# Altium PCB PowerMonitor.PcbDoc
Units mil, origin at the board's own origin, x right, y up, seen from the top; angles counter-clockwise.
Board outline 3500 x 2200 mil, 2 copper layers (Top Layer, Bottom Layer); 24 components, 15 nets, 81 pads, 2 vias.
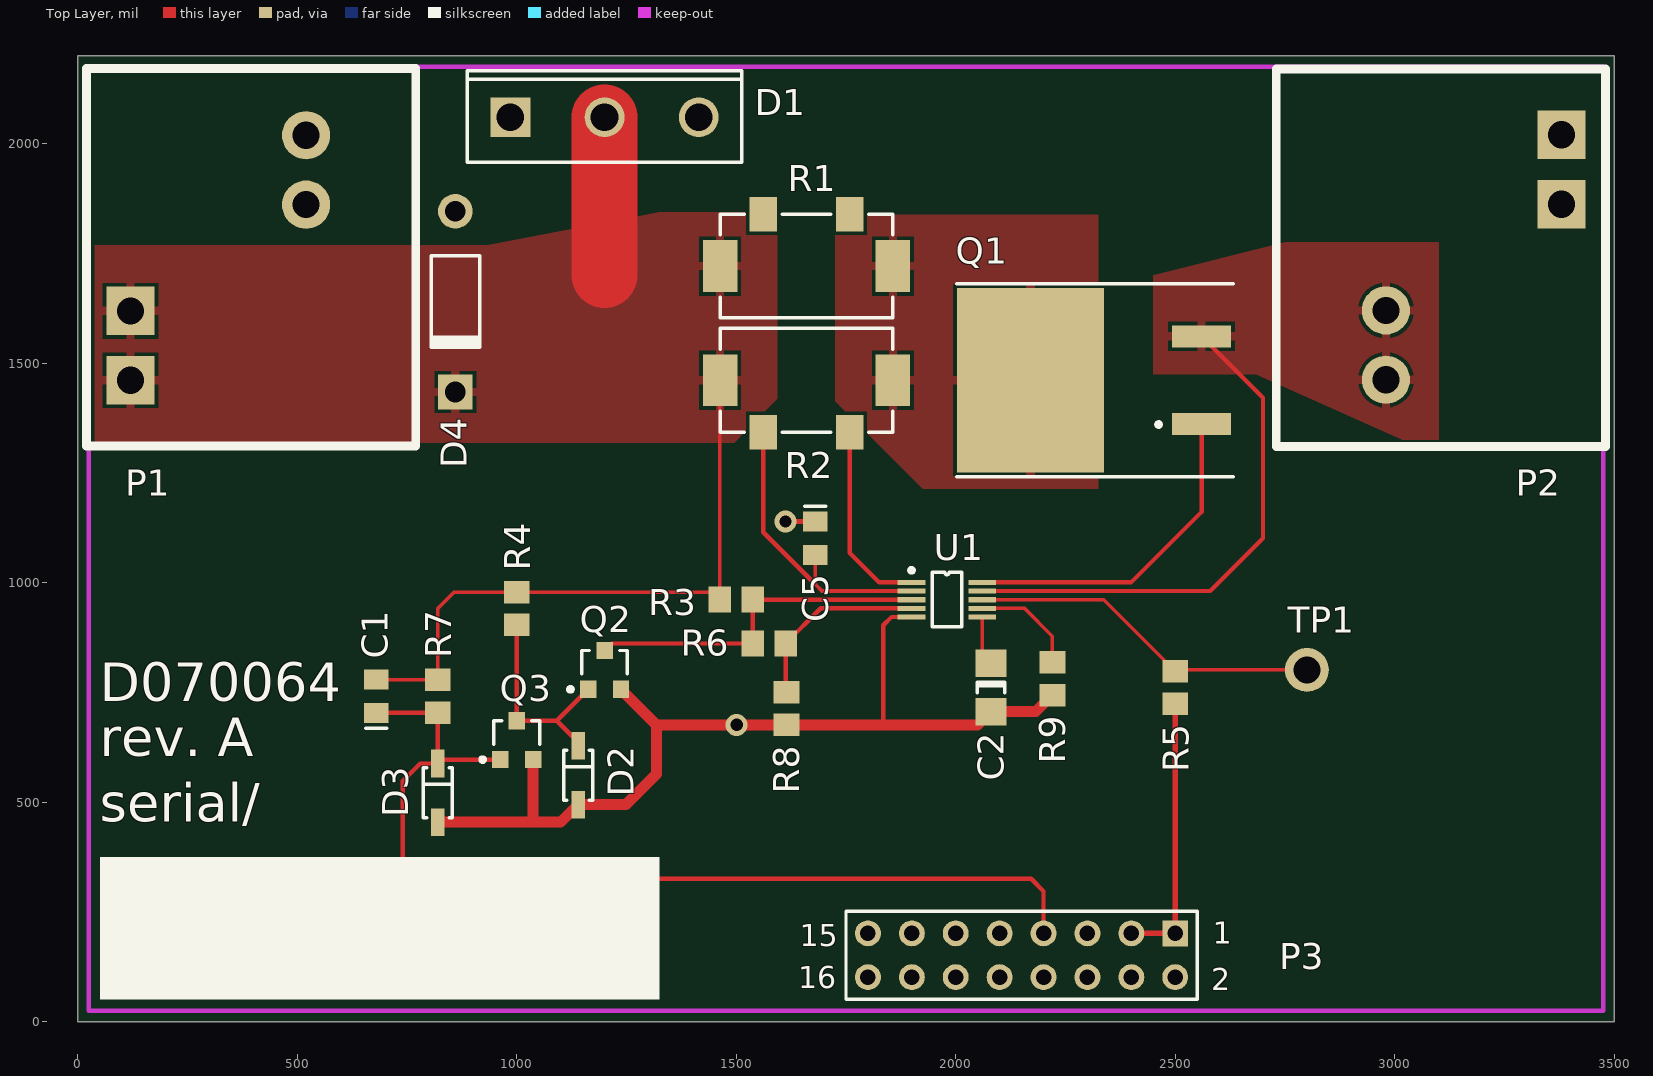
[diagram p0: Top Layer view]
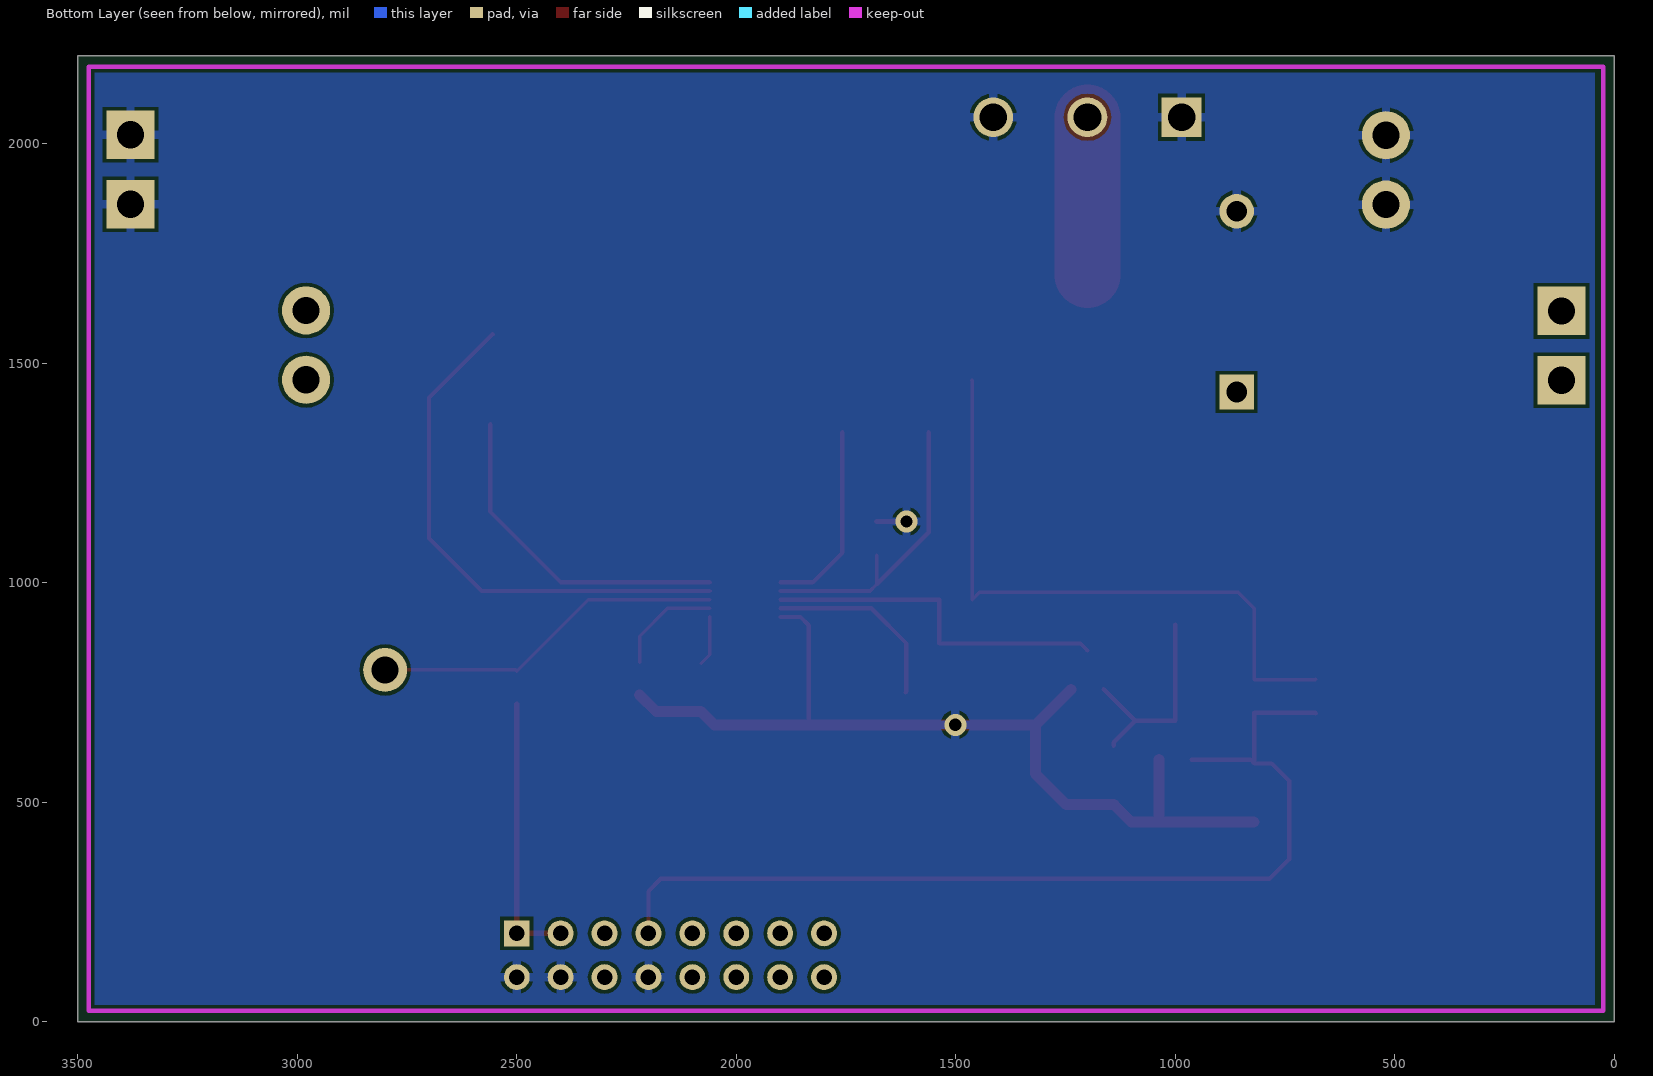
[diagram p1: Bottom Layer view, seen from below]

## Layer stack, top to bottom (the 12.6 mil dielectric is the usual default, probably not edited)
Top Layer: signal copper 1.4
Dielectric: dielectric 12.6, FR-4, Dk 4.8
Bottom Layer: signal copper 1.4

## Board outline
0,0 0,2200 3500,2200 3500,0

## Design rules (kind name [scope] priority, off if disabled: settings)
Clearance [All] p1: gap=8
ComponentClearance [All] p1: gap=10 collisioncheckmode=3 verticalgap=10
Height [All] p1: minheight=0 maxheight=2000 prefheight=500
HoleSize [All] p1: absolutevalues=TRUE maxlimit=125 minlimit=1 maxpercent=80.000 minpercent=20.000
PolygonConnect [All] p1: connectstyle=Relief reliefconductorwidth=20 reliefentries=4 polygonreliefangle="90 Angle"
RoutingVias [All] p1: holewidth=25 width=40 viastyle="Through Hole" minholewidth=28 minwidth=50 maxholewidth=28 maxwidth=50
SolderMaskExpansion [All] p1: expansion=4
TestPointUsage [All] p1: valid=0 allowmultiple=FALSE
Testpoint [All] p1: side=15 testpointundercomponent=TRUE minsize=40 maxsize=100 preferedsize=60 minholesize=0 maxholesize=40 preferedholesize=32 testpointgrid=1 style=1023 order=0123456789
Width [All] p1: maxlimit=400 minlimit=8 preferedwidth=8
16 further rules are at their usual default settings.

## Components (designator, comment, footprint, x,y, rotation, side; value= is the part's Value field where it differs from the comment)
C1 "10p" CC2013-0805 680,741 r90 top
C2 "6.8u" CC3216-1206 2080,761 r270 top
C5 "1n" CC2013-0805 1680,1101 r270 top
D1 "63CPQ100" TO-247AC 1200,2060 r0 top
D2 "zener diode" DO-SOD123 1140,561 r90 top
D3 "zener diode" DO-SOD123 820,521 r90 top
D4 "zener diode" DO-41 860,1640 r270 top
P1 "TBlock_10.16_2" TBLOCK-10.16-2 120,1461 r90 top
P2 "TBlock_10.16_2" TBLOCK-10.16-2 3380,2020 r270 top
P3 "Header 8X2" HDR2X8 2500,201 r180 top
Q1 "FDB3632" D2PAK 2380,1461 r90 top
Q2 "BSS123" SO-G3/C2.25 1200,801 r0 top
Q3 "BSS123" SO-G3/C2.25 1000,641 r0 top
R1 "0.01" RW10862-4325 1660,1721 r180 top
R2 "0.005" RW10862-4325 1660,1461 r0 top
R3 "100K" CR2012-0805 1500,961 r180 top
R4 "100K" CR2012-0805 1000,941 r90 top
R5 "20K" CR2012-0805 2500,761 r270 top
R6 "6.04K" CR2012-0805 1575,861 r180 top
R7 "100K" CR2012-0805 820,741 r90 top
R8 "3.9K" CR2012-0805 1614,713 r90 top
R9 "20K" CR2012-0805 2220,781 r90 top
TP1 "Testpoint" TP1 2800,801 r0 top
U1 "LM5069" TSSO3x5-G10 1980,961 r270 top

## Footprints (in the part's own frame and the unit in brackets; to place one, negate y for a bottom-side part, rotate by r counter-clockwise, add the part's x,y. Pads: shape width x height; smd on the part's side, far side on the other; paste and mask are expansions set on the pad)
CC2013-0805 [mm] "Chip Capacitor; Body 2.0 x 1.3 mm (LxW typ)"
  rect 1.15x1.4 smd: 1(-0.975,0) 2(0.975,0)
  silkscreen extent -1.85,-0.6 -1.85,0.6
CC3216-1206 [mm] "Chip Capacitor; Body 3.2 x 1.6 mm (LxW typ)"
  rect 1.6x1.8 smd: 1(-1.4,0) 2(1.4,0)
  silkscreen extent -0.3,-0.8 0.3,0.8
CR2012-0805 [mm] "Chip Resistor; Body 2.0 x 1.3 mm (LxW typ)"
  rect 1.3x1.5 smd: 1(-0.95,0) 2(0.95,0)
D2PAK [mil] "D2-PAK/TO-263-AB; 3 Leads (1 Cropped); Body 15.5 (inc. leads) x 10.5 mm (LxW max)"
  rect 50x135 smd: 1(-100,-180) 3(100,-180)
  rect 420x335 smd: 2(0,210)
  silkscreen extent -219,-252 219,378
DO-41 [mm] "Diode, Axial; Body 5.2 x 2.7 mm (LxDia. max), Lead Dia. 0.86 mm (max)"
  round 2 hole 1.2: 1(-5.23,0)
  rect 2x2 hole 1.2: 2(5.23,0)
  silkscreen extent -2.65,-1.4 2.75,1.4
DO-SOD123 [mm] "SOD-123; 2 Leads; Body 2.7 x 1.6 mm, (LxW)"
  rect 1.6x0.8 smd: 1(-1.7,0) 2(1.7,0)
  silkscreen extent -1.45,-0.85 1.45,0.85
HDR2X8 [mm] "Connector; Header; 8x2 Position"
  rect 1.5x1.5 hole 0.9: 1(0,0)
  round 1.5 hole 0.9: 2(0,2.54) 3(2.54,0) 4(2.54,2.54) 5(5.08,0) 6(5.08,2.54) 7(7.62,0) 8(7.62,2.54) 9(10.16,0) 10(10.16,2.54) 11(12.7,0) 12(12.7,2.54) 13(15.24,0) 14(15.24,2.54) 15(17.78,0) 16(17.78,2.54)
  silkscreen extent -1.27,-1.27 19.05,3.81
RW10862-4325 [mm] "Current Sense Resistor; Body 10.8 x 6.2 mm (LxW typ)"
  rect 2x3 smd: 1(-5,0) 4(5,0)
  rect 1.6x2 smd: 2(-2.5,-3) 3(2.5,-3)
  silkscreen extent -5,-3 5,3
SO-G3/C2.25 [mm] "SOT-23; 3 Leads; Body 3.0 x 2.5 mm, inc. leads (LxW max)"
  rect 0.95x1 smd: 1(-0.95,-1.125) 2(0.95,-1.125) 3(0,1.125)
  silkscreen extent -2.1,-1.25 1.32,1.13
TBLOCK-10.16-2 [mil] "Terminal Block, 10.16mm, 2pin"
  rect 110x110 hole 62: 1(0,0) 1(158,0)
  round 110 hole 62: 2(400,-400) 2(558,-400)
  silkscreen extent -150,-650 710,100
TO-247AC [mm] "SIP with Mounting Hole; 3 Leads; Body 20 x 15.6 x 5 mm (typ); Pitch 5.45 mm"
  rect 2.3x2.3 hole 1.6: 1(-5.45,0)
  round 2.3 hole 1.6: 2(0,0) 3(5.45,0)
  silkscreen extent -7.95,-2.6 7.95,2.7
TP1 [mm] "Testpoint pin"
  round 2.54 hole 1.58: 1(0,0)
TSSO3x5-G10 [mm] "Shrink Small Outline; 10 Leads; Body Width 3 mm; Pitch 0.5 mm"
  rect 0.297x1.6 smd: 1(-1,-2.05) 2(-0.5,-2.05) 3(0,-2.05) 4(0.5,-2.05) 5(1,-2.05) 6(1,2.05) 7(0.5,2.05) 8(0,2.05) 9(-0.5,2.05) 10(-1,2.05)
  silkscreen extent -1.82,-2.17 1.58,0.85

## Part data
C1 C2 C5: library part ChipCap, "Capacitor, surface mount"
D1: library part 30CPQ100, "Schottky Rectifier"
D2 D3 D4: library part DIODE_ZENER, "Single zener diode"
P1 P2: "Terminal block, 10.16mm, 2-Pin"
P3: "Header, 8-Pin, Dual row"
Q1: library part MOSFET-N, "Power MOSFET, N-channel"
Q2 Q3: library part FDV301N, "FDV301N, Digital FET, N-channel, SOT23"
R1 R2: library part RW1S0CK, "Four-Terminal Current Sense Resistor"
R3 R4 R5 R6 R7 R8 R9: library part Res2, "Resistor"
TP1: library part TP_SIGNAL, "Testpoint, yellow"
U1: "Positive High Voltage Hot Swap / Inrush Current  Controller with Power Limiting"

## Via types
v1: diameter 50, hole 28, Top Layer to Bottom Layer, 2 vias

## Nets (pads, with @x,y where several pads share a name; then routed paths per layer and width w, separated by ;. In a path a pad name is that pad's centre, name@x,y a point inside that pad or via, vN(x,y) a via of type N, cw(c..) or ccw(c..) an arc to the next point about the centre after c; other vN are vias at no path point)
12V: P3.1 P3.3 R5.2 | length 622.6
  Top Layer w12: P3.3 P3.1 R5.2
FAIL: C1.1 D3.2 P3.7 Q3.1 R7.1 | length 2263.1
  Top Layer w10: C1.1 680.98,703.6 R7.1 D3.2 ; Q3.1 828.78,596.71 D3.2 ; P3.7 2200,297 2172,325 785,325 740,370 740,548 779.93,587.93 D3.2
GND: C2.2 C5.1 D1.1 D1.3 D2.1 D3.1 D4.1 P1.2 P2.1 P3.2 P3.4 P3.8 Q2.2 Q3.2 R8.1 R9.1 U1.5 | length 2208.6
  Top Layer w10: 1835,675.6 1835,902.84 1853.8,921.63 U1.5
  Top Layer w12: v1(1612,1139) C5.1
  Top Layer w25: D3.1 1100,454.07 D2.1 1249.07,494.07 1318.51,563.51 1318.51,675.6 ; 1037.4,455.67 Q3.2 ; Q2.2 1318.51,675.6 ; R9.1 2182.28,705.88 C2.2 2049.72,675.6 1318.51,675.6
  other v1: 1501,676
NetC1_2: C1.2 D1.2 D4.2 P1.1 R1.4 R2.1 R3.2 R4.2 R7.2 | length 1827.5
  Top Layer w8: C1.2 680.98,778.4 R7.2 820,941 857.4,978.4 1445.2,978.4 R3.2 1462.6,1460.45 R2.1
  Top Layer w150: 1200,1701 D1.2
NetC2_1: C2.1 U1.6 | length 113.5
  Top Layer w8: U1.6 2060.71,835.41 C2.1
NetC5_2: C5.2 R2.2 U1.2 | length 688.2
  Top Layer w8: C5.2 1680,996 1695.32,980.68
  Top Layer w10: R2.2 1561.57,1114.43 1680,996 ; 1695.32,980.68 U1.2
NetD2_2: D2.2 Q2.1 Q3.3 R4.1 | length 488.1
  Top Layer w10: R4.1 Q3.3 1091.18,685.29 ; D2.2 1140,636.47 1091.18,685.29 ; Q2.1 1091.18,685.29
NetP2_2: P2.2 Q1.3 U1.9 | length 1214.2
  Top Layer w10: U1.9 2579.69,980.68 2700,1101 2700,1421 Q1.3@2555,1566
NetQ1_1: Q1.1 U1.10 | length 765.8
  Top Layer w10: U1.10 2399.37,1000.37 2560,1161 Q1.1
NetQ1_2: Q1.2 R1.1 R2.4
NetQ2_3: Q2.3 R3.1 R6.2 U1.3 | length 805.7
  Top Layer w10: Q2.3 1215.91,861.2 1537.4,861.2 R3.1 U1.3
NetR2_3: R2.3 U1.1 | length 444
  Top Layer w10: R2.3 1758.43,1067.57 1825.63,1000.37 U1.1
NetR5_1: R5.1 TP1.1 U1.8 | length 807.7
  Top Layer w8: U1.8 2337.4,961 R5.1 2502.6,801 TP1.1
NetR6_1: R6.1 R8.2 U1.4 | length 431.4
  Top Layer w10: R8.2 1612.4,752 R6.1 1692.72,941.32 U1.4
NetR9_2: R9.2 U1.7 | length 245.1
  Top Layer w8: U1.7 2156.69,941.32 2220,878 R9.2
pads on no net: P3.5 P3.6 P3.9 P3.10 P3.11 P3.12 P3.13 P3.14 P3.15 P3.16 R1.2 R1.3

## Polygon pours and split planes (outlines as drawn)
NetQ1_2 on Top Layer "NETQ1_2" (solid): 1725,1763.25 1725,1413.25 1925,1213.25 2325,1213.25 2325,1838.25 1725,1838.25
NetP2_2 on Top Layer "NETP2_2" (solid): 2450,1700 2450,1475 2683.33,1475 3016.67,1325 3100,1325 3100,1775 2750,1775
NetC1_2 on Top Layer "NETC1_2" (solid): 1592.84,1843.28 1592.84,1418.28 1494.85,1318.28 25,1318.28 25,1768.28 931.41,1768.28 1323.37,1843.28
GND on Bottom Layer "GND" (solid): 315.08,2175 3475,2175 3475,25 44.23,25 44.23,2175

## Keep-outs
Keep-Out Layer:
  lines w10: 25,25 25,2175 3475,2175 3475,25 25,25

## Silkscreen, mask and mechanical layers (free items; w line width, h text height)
Top Overlay:
  rectangle: 50,50 1325,375
  text "D070064" at 50,700 h150
  text "rev. A" at 50,575 h150
  text "serial/" at 50,425 h150
Mechanical 1:
  the board outline again, w8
